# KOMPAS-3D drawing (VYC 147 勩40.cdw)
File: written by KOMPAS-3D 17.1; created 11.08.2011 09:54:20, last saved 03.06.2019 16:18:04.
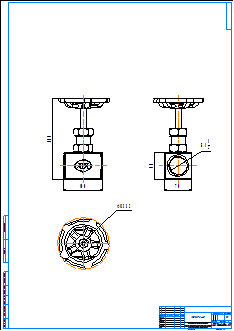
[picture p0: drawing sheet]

Sheet 1: A1, portrait

Title block, sheet 1: name: VYC 147 Ду40; material: Внимание! Данный продукт является объектом авторского права ООО «Торговый Дом АДЛ». / Запрещается изменение, копирование, распространение / (в том числе путем копирования на другие сайты и ресурсы в Интернете) / или любое иное использование информации и объектов без предварительного / согласия правообладателя (ООО «Торговый Дом АДЛ»).; scale: 1:1; sheets: 1; organisation: ООО "Торговый дом АДЛ"; sheet format: A1; stored path: \\adlc.lan\data\АДЛ_ПКД\3D-модели\Поставщики\VYC Industrial\VYC 147\KOMPAS 2D\VYC 147 Ду40.cdw

Views: Спереди 1, Проекционный вид 2, Проекционный вид 3
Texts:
  bsv
  adl
Dimensions and other numbers on the sheet: 100; 207; 70; 133,32; 1:1; 1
